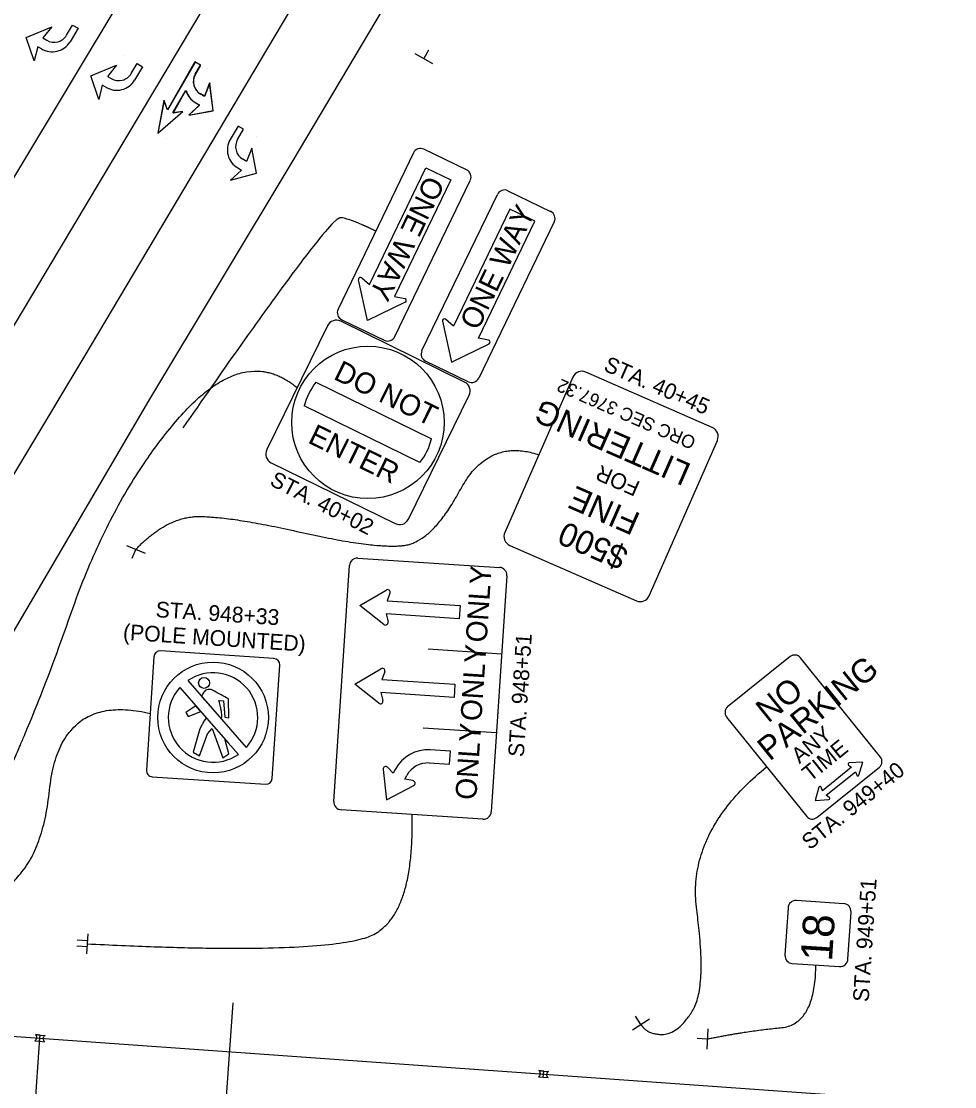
# Model space of a CAD drawing. Extents: x 1847379 to 1850904, y 217032 to 220169.
# Drawn here: x 1848981.8 to 1849129.7, y 218877.1 to 219045.9 of the extents above; entities that cross this region are included whole.
import ezdxf

# ---------------------------------------------------------------- set-up
doc = ezdxf.new("R2010")
doc.units = 0
for name, color, linetype in [('BR_P_Gen_Approach_Slab_Hidden', 7, 'Continuous'), ('BR_P_Gen_Phase_Construction', 7, 'Continuous'), ('PM_P_Cells', 7, 'Continuous'), ('PM_P_Edge_Line', 7, 'Continuous'), ('PM_P_Stop_Line', 7, 'Continuous'), ('PM_X_Cells', 7, 'Continuous'), ('PM_X_Channelizing_Line', 7, 'Continuous'), ('SN_X_Public', 7, 'Continuous'), ('SN_X_Text', 7, 'Continuous')]:
    doc.layers.add(name, color=color, linetype=linetype)

msp = doc.modelspace()

# ---------------------------------------------------------------- linework, layer by layer
at = {"layer": 'BR_P_Gen_Approach_Slab_Hidden'}
for p, q in [((1849024.83, 219023.84), (1849065.83, 219093.02)), ((1849001.98, 218985.74), (1849024.83, 219023.84)), ((1848962.84, 218919.07), (1849001.98, 218985.74))]:
    msp.add_line(p, q, dxfattribs=at)
at = {"layer": 'BR_P_Gen_Phase_Construction'}
msp.add_line((1849015.28, 218890.32), (1849009.23, 218805.57), dxfattribs=at)
at = {"layer": 'PM_P_Cells'}
for p, q in [((1849009.32, 219039.46), (1849004.95, 219031.88)), ((1849010.19, 219038.96), (1849009.32, 219039.46)), ((1849009.35, 219037.51), (1849010.19, 219038.96)), ((1849011.2, 219038.38), (1849011.2, 219038.38)), ((1849011.63, 219036.13), (1849010.8, 219034.02)), ((1849012.18, 219031.75), (1849011.63, 219036.13)), ((1849004.38, 219033.37), (1849003.38, 219028.17)), ((1849004.95, 219031.88), (1849004.38, 219033.37)), ((1849009.42, 219032.97), (1849010, 219032.64)), ((1849010.8, 219034.02), (1849010.19, 219034.37)), ((1849003.38, 219028.17), (1849007.38, 219031.63)), ((1849007.38, 219031.63), (1849005.81, 219031.38)), ((1849010, 219032.64), (1849008.3, 219031.03)), ((1849008.3, 219031.03), (1849012.18, 219031.75)), ((1849004.82, 219027.33), (1849004.82, 219027.33)), ((1848983.9, 218884.33), (1848984.67, 218884.26)), ((1848983.9, 218884.33), (1848984.67, 218884.26)), ((1848984.76, 218885.23), (1848983.99, 218885.3)), ((1848983.99, 218885.3), (1848984.76, 218885.23)), ((1848984.67, 218884.26), (1848984.76, 218885.23)), ((1848984.76, 218885.23), (1848985.53, 218885.16)), ((1848984.67, 218884.26), (1848985.44, 218884.19)), ((1849064.56, 218879.54), (1849063.79, 218879.61)), ((1849063.79, 218879.61), (1849064.56, 218879.54)), ((1849064.47, 218878.57), (1849064.56, 218879.54)), ((1849064.56, 218879.54), (1849065.33, 218879.47)), ((1849063.7, 218878.64), (1849064.47, 218878.57)), ((1849063.7, 218878.64), (1849064.47, 218878.57)), ((1849064.47, 218878.57), (1849065.24, 218878.5))]:
    msp.add_line(p, q, dxfattribs=at)
msp.add_lwpolyline([(1849005.81, 219031.38), (1849007.86, 219034.94)], dxfattribs=at)
for centre, radius, start, end in [((1849011.34, 219036.36), 2.3, 149.9979, 239.9979), ((1849011.02, 219035.84), 3.28, 195.9514, 240.9064), ((1848983.65, 218884.84), 0.576, 296.8063, 52.8586), ((1848983.65, 218884.84), 0.576, 296.8063, 52.8586), ((1848985.79, 218884.65), 0.576, 116.8063, 232.8586), ((1849063.44, 218879.15), 0.576, 296.8063, 52.8586), ((1849063.44, 218879.15), 0.576, 296.8063, 52.8586), ((1849065.58, 218878.96), 0.576, 116.8063, 232.8586)]:
    msp.add_arc(centre, radius, start, end, dxfattribs=at)
at = {"layer": 'PM_P_Edge_Line'}
msp.add_line((1848960.09, 218886.51), (1849497.6, 218848.14), dxfattribs=at)
at = {"layer": 'PM_P_Stop_Line'}
msp.add_line((1848983.04, 218860.81), (1848984.72, 218884.75), dxfattribs=at)
at = {"layer": 'PM_X_Cells'}
for p, q in [((1848982.53, 219043.36), (1848986.62, 219045.03)), ((1848986.62, 219045.03), (1848985.19, 219043.28)), ((1848988.94, 219043.72), (1848989.89, 219045.32)), ((1848990.75, 219044.81), (1848989.49, 219042.68)), ((1848989.89, 219045.32), (1848990.75, 219044.81)), ((1848983.8, 219039.63), (1848982.53, 219043.36)), ((1848985.19, 219043.28), (1848985.79, 219042.92)), ((1848984.37, 219041.9), (1848983.8, 219039.63)), ((1848984.95, 219041.56), (1848984.37, 219041.9)), ((1848998.11, 219040.43), (1848998.11, 219040.43)), ((1848983.8, 219039.63), (1848983.8, 219039.63)), ((1848992.76, 219037.28), (1848996.85, 219038.95)), ((1848996.85, 219038.95), (1848995.42, 219037.19)), ((1848999.17, 219037.64), (1849000.12, 219039.24)), ((1849000.98, 219038.73), (1848999.72, 219036.6)), ((1849000.12, 219039.24), (1849000.98, 219038.73)), ((1849009.28, 219039.48), (1849004.93, 219031.89)), ((1849010.15, 219038.98), (1849009.28, 219039.48)), ((1849009.31, 219037.53), (1849010.15, 219038.98)), ((1849011.16, 219038.41), (1849011.16, 219038.41)), ((1848994.04, 219033.55), (1848992.76, 219037.28)), ((1848995.42, 219037.19), (1848996.02, 219036.83)), ((1848994.6, 219035.81), (1848994.04, 219033.55)), ((1848995.18, 219035.47), (1848994.6, 219035.81)), ((1849011.6, 219036.16), (1849010.78, 219034.05)), ((1849012.17, 219031.78), (1849011.6, 219036.16)), ((1848994.04, 219033.55), (1848994.04, 219033.55)), ((1849004.36, 219033.37), (1849003.38, 219028.17)), ((1849004.93, 219031.89), (1849004.36, 219033.37)), ((1849009.4, 219032.99), (1849009.98, 219032.66)), ((1849010.78, 219034.05), (1849010.17, 219034.4)), ((1849003.38, 219028.17), (1849007.37, 219031.64)), ((1849007.37, 219031.64), (1849005.8, 219031.39)), ((1849009.98, 219032.66), (1849008.29, 219031.05)), ((1849008.29, 219031.05), (1849012.17, 219031.78)), ((1849016.13, 219029.32), (1849014.87, 219027.19)), ((1849016.04, 219027.21), (1849016.99, 219028.81)), ((1849016.99, 219028.81), (1849016.13, 219029.32)), ((1849004.83, 219027.34), (1849004.83, 219027.34)), ((1849019, 219027.62), (1849019, 219027.62)), ((1849018.31, 219025.8), (1849017.45, 219023.7)), ((1849019.05, 219021.83), (1849018.31, 219025.8)), ((1849017.45, 219023.7), (1849016.85, 219024.06)), ((1849016.64, 219022.33), (1849014.92, 219020.74)), ((1849014.92, 219020.74), (1849019.05, 219021.83)), ((1849016.06, 219022.67), (1849016.64, 219022.33)), ((1849014.92, 219020.74), (1849014.92, 219020.74))]:
    msp.add_line(p, q, dxfattribs=at)
msp.add_lwpolyline([(1849005.8, 219031.39), (1849007.84, 219034.95)], dxfattribs=at)
for centre, radius, start, end in [((1848986.96, 219044.89), 2.3, 239.3394, 329.3394), ((1848986.66, 219044.36), 3.28, 238.4309, 329.3394), ((1848996.9, 219038.27), 3.28, 238.4309, 329.3394), ((1848997.2, 219038.81), 2.3, 239.3394, 329.3394), ((1849011.31, 219036.39), 2.3, 150.2118, 240.2118), ((1849010.99, 219035.87), 3.28, 196.1652, 241.1203), ((1849017.69, 219025.52), 3.28, 149.3394, 240.2479), ((1849018.02, 219026.04), 2.3, 149.3394, 239.3394)]:
    msp.add_arc(centre, radius, start, end, dxfattribs=at)
at = {"layer": 'PM_X_Channelizing_Line'}
for points in [[(1848919.1, 218918.16), (1848944.27, 218960.56), (1848972.34, 219007.48), (1849015.24, 219078.84), (1849034.6, 219111.78), (1849062.58, 219158.93), (1849078.71, 219187.23), (1849099.56, 219230.42), (1849123.53, 219290.46)], [(1848931.59, 218915.21), (1848955.27, 218955.41), (1848981.8, 218999.65), (1849029.93, 219080.35), (1849061.68, 219133.31), (1849077.82, 219161.54), (1849103.89, 219209.58), (1849122.08, 219251.34), (1849135.29, 219287.48)], [(1848943.75, 218912.35), (1848965.51, 218949.03), (1848991.71, 218992.7), (1849039.97, 219073.89), (1849071.48, 219127.17)]]:
    msp.add_lwpolyline(points, dxfattribs=at)
at = {"layer": 'SN_X_Public'}
for p, q in [((1849045.55, 219039.99), (1849046.33, 219041.38)), ((1849046.95, 219039.2), (1849044.16, 219040.77)), ((1849036.96, 219004.19), (1849045.89, 219022.71)), ((1849045.89, 219022.71), (1849049.83, 219020.81)), ((1849049.83, 219020.81), (1849040.9, 219002.29)), ((1849059.2, 219016.13), (1849050.26, 218997.62)), ((1849063.14, 219014.23), (1849059.2, 219016.13)), ((1849054.2, 218995.72), (1849063.14, 219014.23)), ((1849036.63, 218998.49), (1849035.19, 219004.95)), ((1849035.7, 219005.26), (1849036.96, 219004.19)), ((1849042.59, 219001.38), (1849036.63, 218998.49)), ((1849040.9, 219002.29), (1849042.52, 219001.97)), ((1849048.49, 218998.38), (1849049.94, 218991.91)), ((1849050.26, 218997.62), (1849049, 218998.69)), ((1849049.94, 218991.91), (1849055.89, 218994.81)), ((1849055.82, 218995.4), (1849054.2, 218995.72)), ((1849028.45, 218988.71), (1849046.77, 218979.72)), ((1849044.94, 218975.97), (1849026.61, 218984.96)), ((1848998.44, 218962.85), (1849001.4, 218961.62)), ((1848999.92, 218962.23), (1848999.3, 218960.76)), ((1849035.43, 218953.31), (1849039.58, 218955.78)), ((1849040.18, 218955.27), (1849039.72, 218954.07)), ((1849039.72, 218954.07), (1849051.29, 218953.3)), ((1849039.22, 218950.31), (1849035.43, 218953.31)), ((1849051.16, 218951.22), (1849039.58, 218951.99)), ((1849039.58, 218951.99), (1849039.88, 218950.74)), ((1849051.29, 218953.3), (1849051.16, 218951.22)), ((1849046.25, 218946.43), (1849057.89, 218945.67)), ((1849034.6, 218940.83), (1849038.76, 218943.3)), ((1849039.36, 218942.8), (1849038.89, 218941.59)), ((1849008.14, 218941.42), (1849017.42, 218930.83)), ((1849038.4, 218937.84), (1849034.6, 218940.83)), ((1849038.89, 218941.59), (1849050.47, 218940.83)), ((1849050.47, 218940.83), (1849050.33, 218938.75)), ((1849010.33, 218938.93), (1849010.42, 218938.82)), ((1849010.42, 218938.82), (1849013.43, 218935.39)), ((1849014.62, 218938.54), (1849014.6, 218938.54)), ((1849014.62, 218938.54), (1849014.6, 218938.54)), ((1849014.65, 218935.54), (1849014.62, 218938.54)), ((1849014.65, 218935.54), (1849014.62, 218938.54)), ((1849050.33, 218938.75), (1849038.76, 218939.51)), ((1849038.76, 218939.51), (1849039.06, 218938.26)), ((1849009.43, 218937.4), (1849007.81, 218936.35)), ((1849009.43, 218937.4), (1849007.81, 218936.35)), ((1849010.2, 218936.52), (1849010.04, 218936.69)), ((1849013.09, 218938.27), (1849013.81, 218938.19)), ((1849013.09, 218938.27), (1849013.81, 218938.19)), ((1849013.81, 218938.19), (1849014.01, 218935.64)), ((1849013.81, 218938.19), (1849014.01, 218935.64)), ((1849007.81, 218936.35), (1849008.18, 218935.74)), ((1849007.81, 218936.35), (1849008.18, 218935.74)), ((1849008.18, 218935.74), (1849010.2, 218936.52)), ((1849008.18, 218935.74), (1849010.2, 218936.52)), ((1849010.76, 218935.05), (1849010.07, 218933.8)), ((1849010.76, 218935.05), (1849010.07, 218933.8)), ((1849011.06, 218935.54), (1849010.76, 218935.05)), ((1849011.06, 218935.54), (1849010.76, 218935.05)), ((1849011.11, 218935.48), (1849011.06, 218935.54)), ((1849013.99, 218932.2), (1849011.11, 218935.48)), ((1849014.01, 218935.64), (1849014.65, 218935.54)), ((1849014.01, 218935.64), (1849014.65, 218935.54)), ((1849010.07, 218933.8), (1849008.99, 218930.09)), ((1849010.07, 218933.8), (1849008.99, 218930.09)), ((1849011.26, 218932.97), (1849012.03, 218933.82)), ((1849011.26, 218932.97), (1849012.03, 218933.82)), ((1849012.03, 218933.82), (1849013.7, 218929.19)), ((1849012.03, 218933.82), (1849013.7, 218929.19)), ((1849045.42, 218933.96), (1849057.07, 218933.19)), ((1849009.99, 218929.52), (1849011.26, 218932.97)), ((1849009.99, 218929.52), (1849011.26, 218932.97)), ((1849014.63, 218929.8), (1849013.99, 218932.2)), ((1849014.63, 218929.8), (1849013.99, 218932.2)), ((1849008.99, 218930.09), (1849009.99, 218929.52)), ((1849008.99, 218930.09), (1849009.99, 218929.52)), ((1849049.77, 218930.23), (1849046.55, 218930.44)), ((1849049.63, 218928.15), (1849049.77, 218930.23)), ((1849013.7, 218929.19), (1849014.63, 218929.8)), ((1849013.7, 218929.19), (1849014.63, 218929.8)), ((1849046.41, 218928.36), (1849049.63, 218928.15)), ((1849115.09, 218928.51), (1849112.93, 218928.37)), ((1849114.49, 218926.43), (1849115.09, 218928.51)), ((1849039.09, 218927.34), (1849039.66, 218922.54)), ((1849040.71, 218926.77), (1849039.8, 218927.69)), ((1849041, 218927.34), (1849040.71, 218926.77)), ((1849113.34, 218927.7), (1849108.71, 218923.97)), ((1849112.85, 218928.04), (1849113.34, 218927.71)), ((1849113.34, 218927.71), (1849113.34, 218927.7)), ((1849113.93, 218926.98), (1849114.15, 218926.42)), ((1849042.55, 218925.81), (1849042.85, 218926.37)), ((1849043.82, 218925.57), (1849042.55, 218925.81)), ((1849111.32, 218925.47), (1849111.32, 218925.47)), ((1849039.66, 218922.54), (1849043.94, 218924.79)), ((1849108.15, 218924.51), (1849107.55, 218922.43)), ((1849108.71, 218923.97), (1849108.49, 218924.53)), ((1849108.71, 218923.97), (1849108.72, 218923.98)), ((1849109.8, 218922.91), (1849109.3, 218923.24)), ((1849107.55, 218922.43), (1849109.71, 218922.58)), ((1848992.31, 218901.29), (1848992.11, 218898.1)), ((1848992.24, 218900.17), (1848990.64, 218900.27)), ((1848992.21, 218899.69), (1848992.21, 218899.69)), ((1848992.18, 218899.21), (1848990.58, 218899.31)), ((1849081.29, 218887.78), (1849078.61, 218886.03)), ((1849079.95, 218886.9), (1849079.07, 218888.24)), ((1849090.53, 218886.21), (1849090.37, 218883.01)), ((1849090.45, 218884.61), (1849088.85, 218884.69))]:
    msp.add_line(p, q, dxfattribs=at)
for points in [[(1849043.9, 219025.06), (1849031.95, 219000.29)], [(1849052.32, 219022.38), (1849045.56, 219025.64)], [(1849040.96, 218995.94), (1849052.9, 219020.71)], [(1849045.25, 218993.72), (1849057.21, 219018.48)], [(1849058.88, 219019.06), (1849065.63, 219015.8)], [(1849066.21, 219014.14), (1849054.26, 218989.37)], [(1849030.29, 218997.66), (1849020.65, 218978.03)], [(1849052.02, 218988.74), (1849032.38, 218998.38)], [(1849032.53, 218998.62), (1849039.29, 218995.36)], [(1849052.59, 218988.79), (1849045.84, 218992.05)], [(1849069.16, 218989.52), (1849058.38, 218964.9)], [(1849091.26, 218981.55), (1849071.22, 218990.32)], [(1849043.1, 218967.01), (1849052.73, 218986.65)], [(1849081.28, 218954.87), (1849092.06, 218979.49)], [(1849021.37, 218975.93), (1849041.01, 218966.3)], [(1849059.19, 218962.84), (1849079.23, 218954.07)], [(1849035.09, 218960.84), (1849057.54, 218959.36)], [(1849031.29, 218922.26), (1849033.76, 218959.68)], [(1849058.7, 218958.03), (1849056.24, 218920.62)], [(1849002.76, 218945.2), (1849001.58, 218927.24)], [(1849021.79, 218944.94), (1849003.83, 218946.13)], [(1849103.62, 218945.24), (1849093.69, 218937.24)], [(1849021.54, 218925.92), (1849022.72, 218943.88)], [(1849117.91, 218929.3), (1849105.2, 218945.07)], [(1849006.87, 218940.31), (1849009.4, 218937.43), (1849010.05, 218936.7), (1849010.04, 218936.69)], [(1849010.42, 218938.82), (1849010.42, 218938.82)], [(1849010.04, 218936.69), (1849009.43, 218937.4), (1849009.43, 218937.4)], [(1849010.04, 218936.69), (1849011.11, 218935.48), (1849014.57, 218931.54), (1849016.16, 218929.72)], [(1849093.52, 218935.65), (1849106.23, 218919.89)], [(1849107.81, 218919.72), (1849117.74, 218927.72)], [(1849109.3, 218923.24), (1849113.93, 218926.97)], [(1849002.51, 218926.17), (1849020.47, 218924.99)], [(1849054.91, 218919.45), (1849032.46, 218920.93)], [(1849112.08, 218906.06), (1849104.59, 218906.55)], [(1849103.27, 218905.39), (1849102.78, 218897.9)], [(1849112.75, 218897.25), (1849113.24, 218904.73)], [(1849103.94, 218896.57), (1849111.42, 218896.08)]]:
    msp.add_lwpolyline(points, dxfattribs=at)
for centre, radius in [((1849036.69, 218982.34), 12.08), ((1849012.15, 218935.57), 8.77), ((1849010.73, 218941.05), 0.864)]:
    msp.add_circle(centre, radius, dxfattribs=at)
for centre, radius, start, end in [((1849045.02, 219024.51), 1.25, 64.2568, 154.2568), ((1849051.78, 219021.26), 1.25, 334.2568, 64.2568), ((1849058.33, 219017.94), 1.25, 64.234, 154.234), ((1849065.09, 219014.68), 1.25, 334.234, 64.234), ((1849035.5, 219005.02), 0.314, 50.0136, 192.6293), ((1849042.45, 219001.66), 0.314, 295.9147, 78.4742), ((1849033.08, 218999.74), 1.25, 154.2568, 244.2568), ((1849031.69, 218996.98), 1.56, 63.8686, 153.8686), ((1849048.8, 218998.45), 0.314, 50.0166, 192.576), ((1849039.83, 218996.49), 1.25, 244.2568, 334.2568), ((1849055.75, 218995.09), 0.314, 295.8614, 78.4772), ((1849046.38, 218993.17), 1.25, 154.234, 244.234), ((1849053.13, 218989.91), 1.25, 244.234, 334.234), ((1849070.6, 218988.89), 1.56, 66.3502, 156.3502), ((1849036.69, 218982.34), 10.42, 142.3317, 165.4056), ((1849051.33, 218987.34), 1.56, 333.8686, 63.8686), ((1849090.63, 218980.12), 1.56, 336.3502, 66.3502), ((1849036.69, 218982.34), 10.42, 322.3317, 345.4056), ((1849022.06, 218977.34), 1.56, 153.8686, 243.8686), ((1849041.7, 218967.7), 1.56, 243.8686, 333.8686), ((1849059.81, 218964.28), 1.56, 156.3502, 246.3502), ((1849035.01, 218959.6), 1.25, 86.2275, 176.2275), ((1849057.46, 218958.12), 1.25, 356.2275, 86.2275), ((1849039.79, 218955.42), 0.417, 338.8657, 120.7438), ((1849079.85, 218955.5), 1.56, 246.3502, 336.3502), ((1849039.48, 218950.64), 0.417, 231.7113, 13.5894), ((1849003.76, 218945.13), 1, 86.2275, 176.2275), ((1849104.32, 218944.36), 1.12, 38.8676, 128.8676), ((1849021.72, 218943.95), 1, 356.2275, 86.2275), ((1849012.15, 218935.57), 7.09, 318.0466, 124.3989), ((1849038.97, 218942.95), 0.417, 338.8657, 120.7438), ((1849012.15, 218935.57), 7.09, 138.0755, 304.4755), ((1849012.15, 218935.57), 7.09, 138.0755, 304.4755), ((1849038.66, 218938.16), 0.417, 231.7113, 13.5894), ((1849094.39, 218936.36), 1.12, 128.8676, 218.8676), ((1849046.17, 218924.62), 5.83, 86.2275, 152.3174), ((1849046.17, 218924.62), 3.75, 86.2275, 152.3289), ((1849112.95, 218928.19), 0.182, 93.7884, 236.5054), ((1849117.03, 218928.59), 1.12, 308.8676, 38.8676), ((1849002.58, 218927.17), 1, 176.2275, 266.2275), ((1849039.5, 218927.39), 0.417, 44.9091, 186.7872), ((1849020.54, 218925.99), 1, 266.2275, 356.2275), ((1849043.74, 218925.16), 0.417, 297.7547, 79.6328), ((1849114.32, 218926.49), 0.182, 201.2298, 343.9469), ((1849108.32, 218924.46), 0.182, 21.2298, 163.9469), ((1849032.54, 218922.18), 1.25, 176.2275, 266.2275), ((1849109.7, 218922.76), 0.182, 273.7884, 56.5054), ((1849054.99, 218920.7), 1.25, 266.2275, 356.2275), ((1849107.1, 218920.59), 1.12, 218.8676, 308.8676), ((1849104.51, 218905.31), 1.25, 86.2508, 176.2508), ((1849112, 218904.82), 1.25, 356.2508, 86.2508), ((1849104.02, 218897.82), 1.25, 176.2508, 266.2508), ((1849111.51, 218897.33), 1.25, 266.2508, 356.2508)]:
    msp.add_arc(centre, radius, start, end, dxfattribs=at)
for points, degree in [([(1849037.92, 219012.67), (1849034.06, 219014.6), (1849030.57, 219014.99), (1849007.37, 218981.48)], 2), ([(1848975.25, 218917.52), (1848982.89, 218932.61), (1848996.11, 218970.77), (1849017.02, 218994.94), (1849025.47, 218987.85)], 2), ([(1848999.92, 218962.23), (1849004.87, 218967.42), (1849014.94, 218967.44), (1849037.55, 218962.35), (1849046.83, 218963.27), (1849055.77, 218979.97), (1849063.77, 218977.21)], 2), ([(1849014.6, 218938.54), (1849013.74, 218938.99), (1849012.4, 218939.71), (1849011.91, 218939.98), (1849011.74, 218940.02), (1849011.57, 218940.03), (1849011.17, 218940.06), (1849010.64, 218939.62), (1849010.45, 218939.19), (1849010.33, 218938.93)], 3), ([(1849014.6, 218938.54), (1849013.74, 218938.99), (1849012.4, 218939.71), (1849011.91, 218939.98), (1849011.74, 218940.02), (1849011.57, 218940.03), (1849011.17, 218940.06), (1849010.64, 218939.62), (1849010.45, 218939.19), (1849010.33, 218938.93)], 3), ([(1848973.85, 218906.18), (1848984.63, 218908.32), (1848987.82, 218939.63), (1849002.17, 218936.22)], 2), ([(1849013.43, 218935.39), (1849013.46, 218935.46), (1849013.54, 218935.66), (1849013.54, 218936.12), (1849013.48, 218936.54), (1849013.33, 218937.27), (1849013.21, 218937.78), (1849013.09, 218938.27)], 3), ([(1849013.43, 218935.39), (1849013.46, 218935.46), (1849013.54, 218935.66), (1849013.54, 218936.12), (1849013.48, 218936.54), (1849013.33, 218937.27), (1849013.21, 218937.78), (1849013.09, 218938.27)], 3), ([(1849079.95, 218886.9), (1849080.94, 218885.33), (1849085.78, 218885.34), (1849090.47, 218892.79), (1849087.12, 218917.34), (1849099.87, 218927.77)], 2), ([(1848992.21, 218899.69), (1849031.7, 218897.72), (1849044.07, 218904.95), (1849043.68, 218920.19)], 2), ([(1849090.45, 218884.61), (1849096.74, 218885.91), (1849107.55, 218886.89), (1849107.68, 218896.33)], 2)]:
    msp.add_open_spline(points, degree=degree, dxfattribs=at)

# ---------------------------------------------------------------- texts
for s, height, rotation, p in [('ONE WAY', 3.333, 244.2568, (1849045.96, 219021.66)), ('ONE WAY', 3.333, 64.234, (1849054.13, 218996.77)), ('DO NOT', 3.333, 333.8686, (1849031.07, 218989.28)), ('ORC SEC 3767.32', 2.0833, 156.3502, (1849088.83, 218979.88)), ('LITTERING', 3.75, 156.3502, (1849088.14, 218975.64)), ('ENTER', 3.333, 333.8686, (1849027.01, 218979.2)), ('FOR', 2.5, 156.3502, (1849079.99, 218972.84)), ('STA. 40+02', 2.5, 332.9001, (1849020.97, 218972.49)), ('FINE', 3.75, 156.3502, (1849080.08, 218967.8)), ('$500', 3.75, 156.3502, (1849078.17, 218962.26)), ('ONLY', 3.333, 86.2275, (1849055.5, 218947.39)), ('STA. 948+33', 2.5, 356.2275, (1849003, 218951.48)), ('(POLE MOUNTED)', 2.5, 356.2275, (1848997.83, 218947.91)), ('STA. 948+51', 2.5, 86.2275, (1849061.39, 218929.26)), ('ONLY', 3.333, 86.2275, (1849054.67, 218934.92)), ('PARKING', 3.75, 38.8676, (1849100.35, 218928.56)), ('NO', 3.75, 38.8676, (1849100.1, 218934.58)), ('ONLY', 3.333, 86.2275, (1849053.85, 218922.44)), ('ANY', 2.5, 38.8676, (1849105.07, 218928.15)), ('TIME', 2.5, 38.8676, (1849106.78, 218925.31)), ('STA. 949+40', 2.5, 38.8676, (1849106.7, 218914.48)), ('STA. 949+51', 2.5, 86.2508, (1849116.03, 218890.43)), ('18', 5, 86.2508, (1849110.22, 218896.84))]:
    msp.add_text(s, height=height, rotation=rotation, dxfattribs=at).set_placement(p)
at = {"layer": 'SN_X_Text'}
msp.add_text('STA. 40+45', height=2.5, rotation=336.3502, dxfattribs=at).set_placement((1849073.88, 218990.62))

doc.saveas('drawing.dxf')
